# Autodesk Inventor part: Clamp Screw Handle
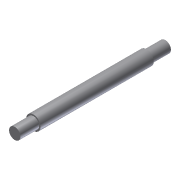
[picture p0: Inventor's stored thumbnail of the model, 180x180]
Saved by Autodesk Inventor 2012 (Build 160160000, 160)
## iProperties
Shininess: 77.0
Length Units: 11269
Angle Units: 11279
Time Units: 11290
Mass Units: 11283
Length Display Precision: 3
Angle Display Precision: 2
Compacted: True
Created: 2002-02
Part Number: Clamp Screw Handle
Document SubType Name: Modeling
Designer: ***
Density: 1 g/cm^3
Material: Default
Density: 0.0
Volumn: 0.0
Area: 0.0
PropertySet Name: Model Information
Control State: 0
Master: False
Checked Out: False
Author: ***
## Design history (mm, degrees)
sketch "Sketch1"
  geometry: L1 (0, 105)-(4, 105); L2 (4, 105)-(4, 92); L3 (4, 92)-(5, 92); L4 (5, 92)-(5, 13); L5 (5, 13)-(4, 13); L6 (4, 13)-(4, 0); L7 (4, 0)-(0, 0); L8 (0, 0)-(0, 105)
  constraints: 16 end point, 5 parallel, 2 equal length, 1 collinear, 1 horizontal, 1 perpendicular
  dimensions: "d0" = 10 diameter of L4 L8; "d1" = 8 diameter of L2 L8; "d2" = 13 distance of L1.end L2.end; "d3" = 79 distance of L3.end L4.end
revolve "Revolution1" sketch "Sketch1" stored, may be unused: angle "d4" = 90 deg
body "Solid1"
